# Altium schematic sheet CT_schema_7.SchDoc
size 277 x 170 mm
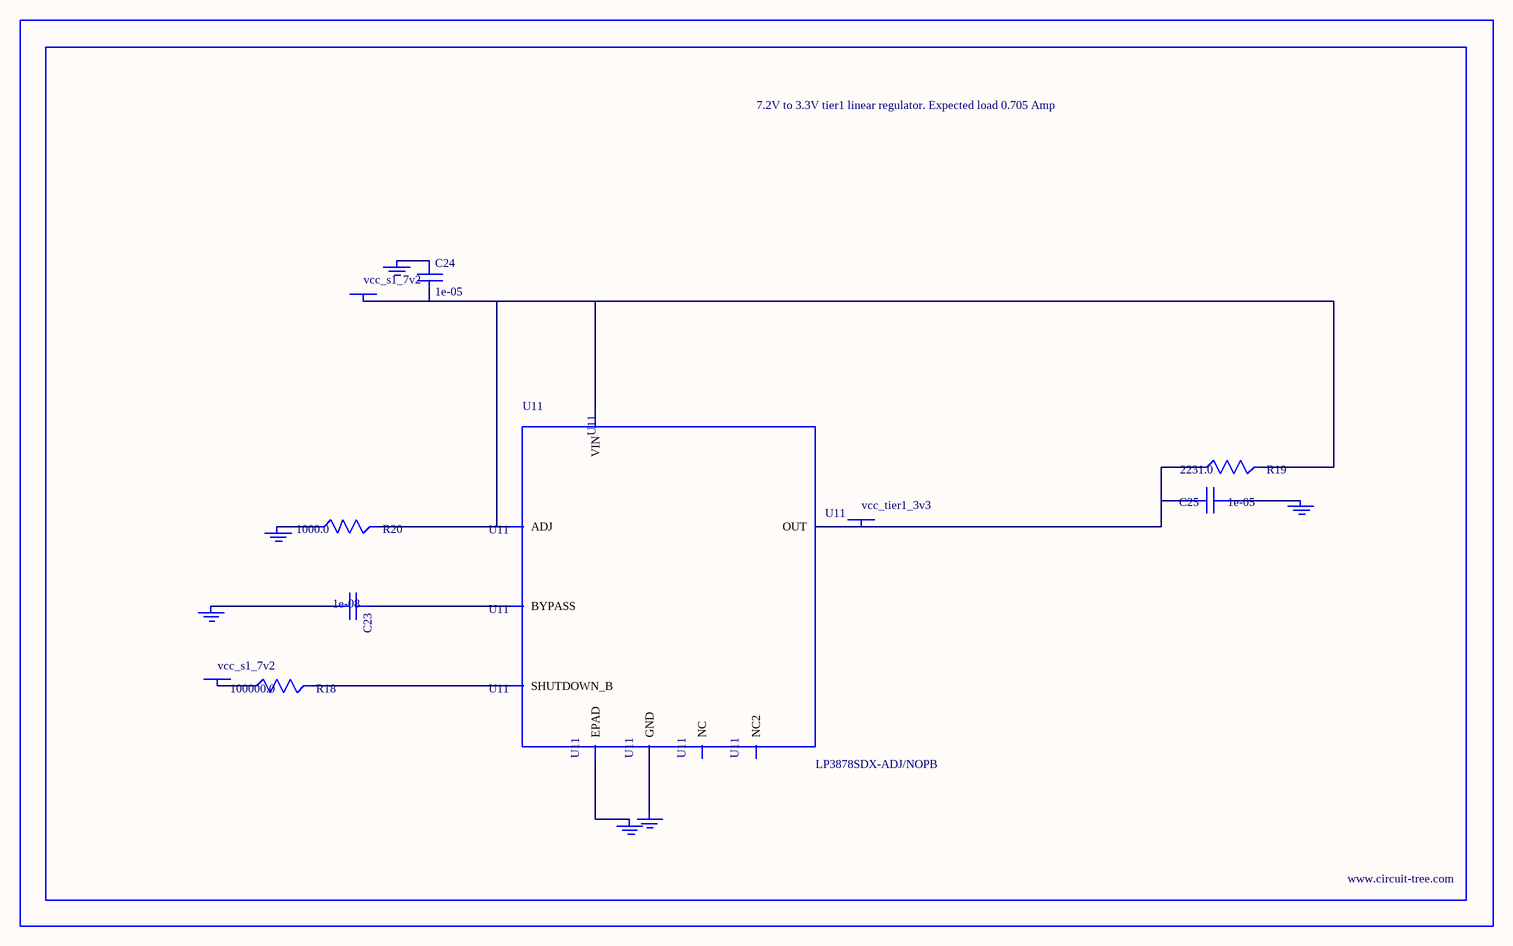
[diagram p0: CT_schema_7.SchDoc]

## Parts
BORDER6  (no value)
C23  1e-08  [C0402]
C24  1e-05  [C1206]
C25  1e-05  [C1210]
GND_INSTANCE_6_0  (no value)
GND_INSTANCE_6_1  (no value)
GND_INSTANCE_6_2  (no value)
GND_INSTANCE_6_3  (no value)
GND_INSTANCE_6_4  (no value)
GND_INSTANCE_6_5  (no value)
POWER_INSTANCE_6_0  vcc_s1_7v2
POWER_INSTANCE_6_1  vcc_s1_7v2
POWER_INSTANCE_6_2  vcc_tier1_3v3
R18  100000.0  [R0603]
R19  2231.0  [R0603]
R20  1000.0  [R0603]
U11  LP3878SDX-ADJ/NOPB  [WSON-8]

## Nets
NetC23_1: C23.1 U11.1(BYPASS)
NetC23_2: C23.2 GND_INSTANCE_6_0.0(GND)
NetC24_1: C24.1 GND_INSTANCE_6_1.0(GND)
NetC24_2: C24.2 POWER_INSTANCE_6_0.0(PWR) R19.2 R20.2 U11.4(VIN) U11.6(ADJ)
NetC25_1: C25.1 GND_INSTANCE_6_2.0(GND)
NetC25_2: C25.2 POWER_INSTANCE_6_2.0(PWR) R19.1 U11.5(OUT)
NetGND_INSTANCE_6_3_0: GND_INSTANCE_6_3.0(GND) R20.1
NetGND_INSTANCE_6_4_0: GND_INSTANCE_6_4.0(GND) U11.PAD(EPAD)
NetGND_INSTANCE_6_5_0: GND_INSTANCE_6_5.0(GND) U11.3(GND)
NetPOWER_INSTANCE_6_1_0: POWER_INSTANCE_6_1.0(PWR) R18.1
NetR18_2: R18.2 U11.8(SHUTDOWN_B)

Not connected (* = marked no-connect by the designer): U11 2(NC) 7(NC2)

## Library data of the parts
BORDER6 = BORDER_PAGE6
C23 = C0402C103K3RAC
C24 = C1206C106K3RACTU
C25 = GRM32DR61E106MA12L
GND_INSTANCE_6_0-GND_INSTANCE_6_5 = GND
POWER_INSTANCE_6_0-POWER_INSTANCE_6_2 = PWR
R18 = RC0603JR-07100KL
R19 = R19
R20 = RC0603JR-071KL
